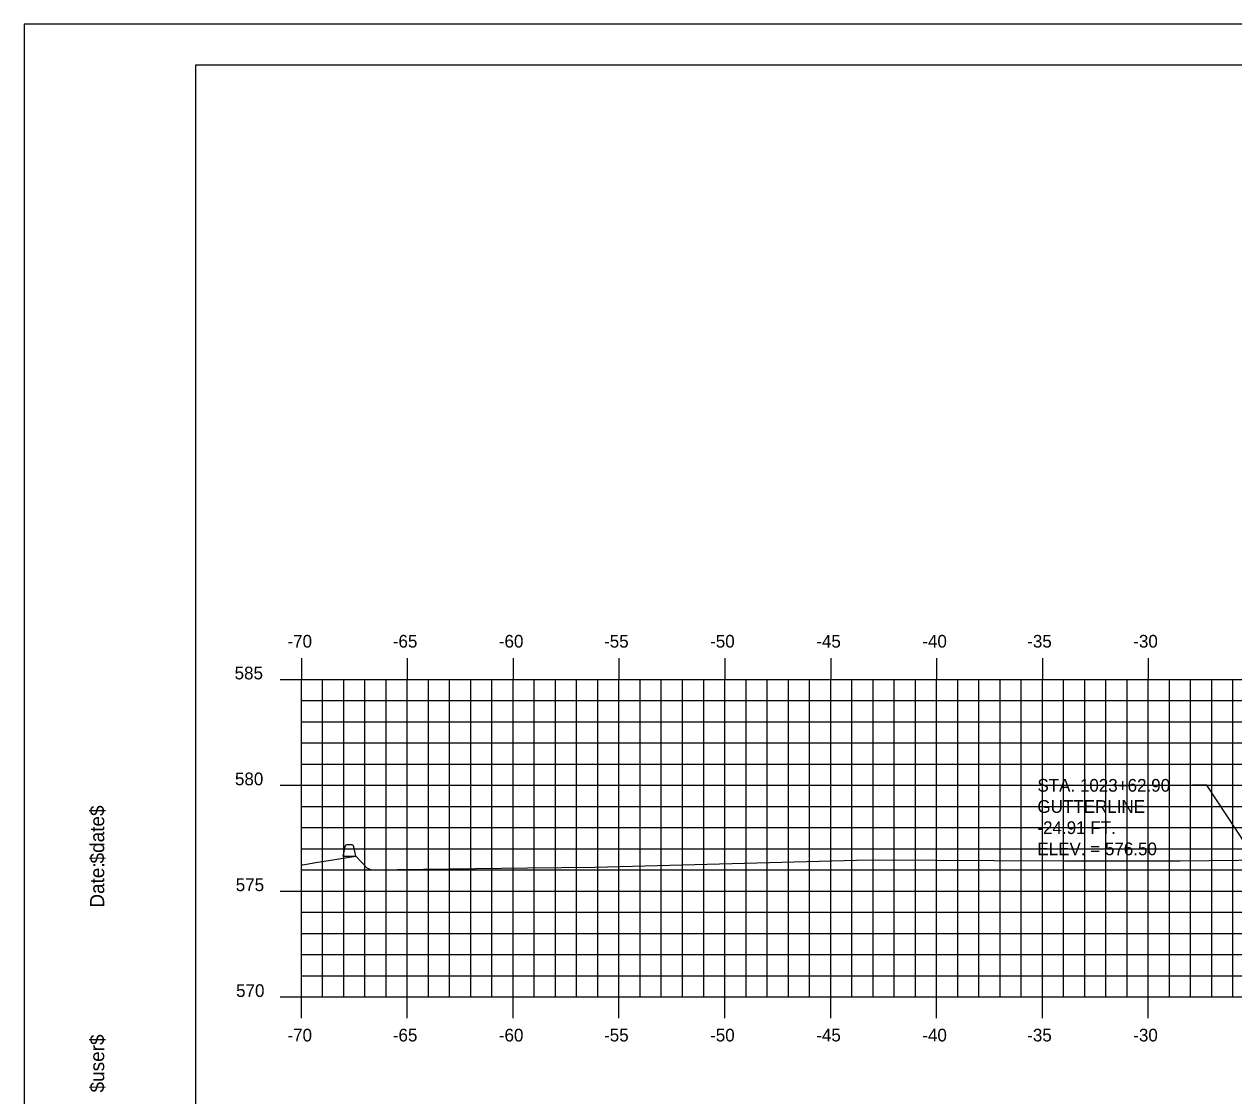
# Model space of a CAD drawing. Extents: x 1048343 to 1048513, y 781387 to 781497.
# Drawn here: x 1048343 to 1048400.2, y 781446.7 to 781497.3 of the extents above; entities that cross this region are included whole.
import ezdxf

# ---------------------------------------------------------------- set-up
doc = ezdxf.new("R2010")
doc.units = 0
for name, color, linetype in [('BORDER', 7, 'Continuous'), ('D_Text_Standard', 7, 'Continuous'), ('H_V ANNOTATION', 7, 'Continuous'), ('MAJOR', 7, 'Continuous'), ('MINOR', 7, 'Continuous'), ('PLOT BOUNDARY', 7, 'Continuous'), ('S_Curb_Type_3', 7, 'Continuous'), ('S_Roadway_Centerline', 7, 'Continuous')]:
    doc.layers.add(name, color=color, linetype=linetype)

msp = doc.modelspace()

# ---------------------------------------------------------------- linework, layer by layer
at = {"layer": 'BORDER'}
msp.add_lwpolyline([(1048351.12, 781390.375), (1048511.12, 781390.375), (1048511.12, 781495.375), (1048351.12, 781495.375)], close=True, dxfattribs=at)
at = {"layer": 'D_Text_Standard'}
msp.add_lwpolyline([(1048401.205, 781457.871), (1048398.888, 781461.371), (1048398.208, 781461.371)], dxfattribs=at)
at = {"layer": 'MAJOR'}
for p, q in [((1048356.119, 781467.377), (1048356.119, 781466.375)), ((1048361.119, 781467.377), (1048361.119, 781466.375)), ((1048366.119, 781467.377), (1048366.119, 781466.375)), ((1048371.119, 781467.377), (1048371.119, 781466.375)), ((1048376.119, 781467.377), (1048376.119, 781466.375)), ((1048381.119, 781467.377), (1048381.119, 781466.375)), ((1048386.119, 781467.377), (1048386.119, 781466.375)), ((1048391.119, 781467.377), (1048391.119, 781466.375)), ((1048396.119, 781467.377), (1048396.119, 781466.375)), ((1048355.117, 781466.375), (1048356.119, 781466.375)), ((1048356.119, 781466.375), (1048496.119, 781466.375)), ((1048356.119, 781451.375), (1048356.119, 781466.375)), ((1048356.119, 781451.375), (1048356.119, 781466.375)), ((1048356.119, 781466.375), (1048496.119, 781466.375)), ((1048361.119, 781451.375), (1048361.119, 781466.375)), ((1048366.119, 781451.375), (1048366.119, 781466.375)), ((1048371.119, 781451.375), (1048371.119, 781466.375)), ((1048376.119, 781451.375), (1048376.119, 781466.375)), ((1048381.119, 781451.375), (1048381.119, 781466.375)), ((1048386.119, 781451.375), (1048386.119, 781466.375)), ((1048391.119, 781451.375), (1048391.119, 781466.375)), ((1048396.119, 781451.375), (1048396.119, 781466.375)), ((1048355.117, 781461.375), (1048356.119, 781461.375)), ((1048356.119, 781461.375), (1048496.119, 781461.375)), ((1048355.117, 781456.375), (1048356.119, 781456.375)), ((1048356.119, 781456.375), (1048496.119, 781456.375)), ((1048355.117, 781451.375), (1048356.119, 781451.375)), ((1048356.119, 781451.375), (1048496.119, 781451.375)), ((1048356.119, 781451.375), (1048496.119, 781451.375)), ((1048356.119, 781450.373), (1048356.119, 781451.375)), ((1048361.119, 781450.373), (1048361.119, 781451.375)), ((1048366.119, 781450.373), (1048366.119, 781451.375)), ((1048371.119, 781450.373), (1048371.119, 781451.375)), ((1048376.119, 781450.373), (1048376.119, 781451.375)), ((1048381.119, 781450.373), (1048381.119, 781451.375)), ((1048386.119, 781450.373), (1048386.119, 781451.375)), ((1048391.119, 781450.373), (1048391.119, 781451.375)), ((1048396.119, 781450.373), (1048396.119, 781451.375))]:
    msp.add_line(p, q, dxfattribs=at)
at = {"layer": 'MINOR'}
for p, q in [((1048357.119, 781451.375), (1048357.119, 781466.375)), ((1048358.119, 781451.375), (1048358.119, 781466.375)), ((1048359.119, 781451.375), (1048359.119, 781466.375)), ((1048360.119, 781451.375), (1048360.119, 781466.375)), ((1048362.119, 781451.375), (1048362.119, 781466.375)), ((1048363.119, 781451.375), (1048363.119, 781466.375)), ((1048364.119, 781451.375), (1048364.119, 781466.375)), ((1048365.119, 781451.375), (1048365.119, 781466.375)), ((1048367.119, 781451.375), (1048367.119, 781466.375)), ((1048368.119, 781451.375), (1048368.119, 781466.375)), ((1048369.119, 781451.375), (1048369.119, 781466.375)), ((1048370.119, 781451.375), (1048370.119, 781466.375)), ((1048372.119, 781451.375), (1048372.119, 781466.375)), ((1048373.119, 781451.375), (1048373.119, 781466.375)), ((1048374.119, 781451.375), (1048374.119, 781466.375)), ((1048375.119, 781451.375), (1048375.119, 781466.375)), ((1048377.119, 781451.375), (1048377.119, 781466.375)), ((1048378.119, 781451.375), (1048378.119, 781466.375)), ((1048379.119, 781451.375), (1048379.119, 781466.375)), ((1048380.119, 781451.375), (1048380.119, 781466.375)), ((1048382.119, 781451.375), (1048382.119, 781466.375)), ((1048383.119, 781451.375), (1048383.119, 781466.375)), ((1048384.119, 781451.375), (1048384.119, 781466.375)), ((1048385.119, 781451.375), (1048385.119, 781466.375)), ((1048387.119, 781451.375), (1048387.119, 781466.375)), ((1048388.119, 781451.375), (1048388.119, 781466.375)), ((1048389.119, 781451.375), (1048389.119, 781466.375)), ((1048390.119, 781451.375), (1048390.119, 781466.375)), ((1048392.119, 781451.375), (1048392.119, 781466.375)), ((1048393.119, 781451.375), (1048393.119, 781466.375)), ((1048394.119, 781451.375), (1048394.119, 781466.375)), ((1048395.119, 781451.375), (1048395.119, 781466.375)), ((1048397.119, 781451.375), (1048397.119, 781466.375)), ((1048398.119, 781451.375), (1048398.119, 781466.375)), ((1048399.119, 781451.375), (1048399.119, 781466.375)), ((1048400.119, 781451.375), (1048400.119, 781466.375)), ((1048356.119, 781465.375), (1048496.119, 781465.375)), ((1048356.119, 781465.375), (1048357.121, 781465.375)), ((1048356.119, 781464.375), (1048496.119, 781464.375)), ((1048356.119, 781464.375), (1048357.121, 781464.375)), ((1048356.119, 781463.375), (1048496.119, 781463.375)), ((1048356.119, 781463.375), (1048357.121, 781463.375)), ((1048356.119, 781462.375), (1048496.119, 781462.375)), ((1048356.119, 781462.375), (1048357.121, 781462.375)), ((1048356.119, 781460.375), (1048496.119, 781460.375)), ((1048356.119, 781460.375), (1048357.121, 781460.375)), ((1048356.119, 781459.375), (1048496.119, 781459.375)), ((1048356.119, 781459.375), (1048357.121, 781459.375)), ((1048356.119, 781458.375), (1048496.119, 781458.375)), ((1048356.119, 781458.375), (1048357.121, 781458.375)), ((1048356.119, 781457.375), (1048496.119, 781457.375)), ((1048356.119, 781457.375), (1048357.121, 781457.375)), ((1048356.119, 781455.375), (1048496.119, 781455.375)), ((1048356.119, 781455.375), (1048357.121, 781455.375)), ((1048356.119, 781454.375), (1048496.119, 781454.375)), ((1048356.119, 781454.375), (1048357.121, 781454.375)), ((1048356.119, 781453.375), (1048496.119, 781453.375)), ((1048356.119, 781453.375), (1048357.121, 781453.375)), ((1048356.119, 781452.375), (1048496.119, 781452.375)), ((1048356.119, 781452.375), (1048357.121, 781452.375))]:
    msp.add_line(p, q, dxfattribs=at)
at = {"layer": 'PLOT BOUNDARY'}
msp.add_lwpolyline([(1048343.026, 781387.316), (1048513.026, 781387.316), (1048513.026, 781497.316), (1048343.026, 781497.316)], close=True, dxfattribs=at)
at = {"layer": 'S_Curb_Type_3'}
for points in [[(1048358.171, 781458.469), (1048358.069, 781458.025), (1048358.694, 781458.025), (1048358.591, 781458.469)], [(1048358.469, 781458.566), (1048358.293, 781458.566)]]:
    msp.add_lwpolyline(points, dxfattribs=at)
for centre, start, end in [((1048358.293, 781458.441), 90, 167.0054), ((1048358.469, 781458.441), 12.9946, 90)]:
    msp.add_arc(centre, 0.125, start, end, dxfattribs=at)
at = {"layer": 'S_Roadway_Centerline'}
msp.add_lwpolyline([(1048356.119, 781457.613), (1048356.189, 781457.617), (1048356.797, 781457.724), (1048358.694, 781458.025), (1048359.226, 781457.455), (1048359.433, 781457.377), (1048359.434, 781457.378), (1048366.803, 781457.47), (1048369.997, 781457.508), (1048382.34, 781457.837), (1048383.363, 781457.858), (1048388.843, 781457.824), (1048392.158, 781457.807), (1048397.617, 781457.799), (1048407.252, 781457.914)], dxfattribs=at)

# ---------------------------------------------------------------- texts
at = {"layer": 'BORDER'}
for s, p in [('$date$', (1048346.805, 781457.681)), ('Date:', (1048346.805, 781455.592)), ('$user$', (1048346.805, 781446.867))]:
    msp.add_text(s, height=0.6696, rotation=90, dxfattribs=at).set_placement(p)
at = {"layer": 'D_Text_Standard'}
for s, p in [('STA. 1023+62.90', (1048390.882, 781461.071)), ('GUTTERLINE', (1048390.882, 781460.071)), ('-24.91 FT.', (1048390.882, 781459.071)), ('ELEV. = 576.50', (1048390.882, 781458.071))]:
    msp.add_text(s, height=0.6, dxfattribs=at).set_placement(p)
at = {"layer": 'H_V ANNOTATION'}
for s, p in [('-70', (1048355.461, 781467.875)), ('-65', (1048360.437, 781467.875)), ('-60', (1048365.445, 781467.875)), ('-55', (1048370.416, 781467.875)), ('-50', (1048375.424, 781467.875)), ('-45', (1048380.437, 781467.875)), ('-40', (1048385.445, 781467.875)), ('-35', (1048390.4, 781467.875)), ('-30', (1048395.408, 781467.875)), ('585', (1048352.965, 781466.375)), ('580', (1048352.981, 781461.375)), ('575', (1048353.019, 781456.375)), ('570', (1048353.035, 781451.375)), ('-70', (1048355.461, 781449.275)), ('-65', (1048360.437, 781449.275)), ('-60', (1048365.445, 781449.275)), ('-55', (1048370.416, 781449.275)), ('-50', (1048375.424, 781449.275)), ('-45', (1048380.437, 781449.275)), ('-40', (1048385.445, 781449.275)), ('-35', (1048390.4, 781449.275)), ('-30', (1048395.408, 781449.275))]:
    msp.add_text(s, height=0.6, dxfattribs=at).set_placement(p)
at = {"layer": 'MAJOR'}
msp.add_text('-', height=0.006, dxfattribs=at).set_placement((1048356.115, 781451.375))
at = {"layer": 'S_Roadway_Centerline'}
for s, p in [('L', (1048383.354, 781457.85)), ('C', (1048383.358, 781457.858))]:
    msp.add_text(s, height=0.0146, dxfattribs=at).set_placement(p)

doc.saveas('drawing.dxf')
